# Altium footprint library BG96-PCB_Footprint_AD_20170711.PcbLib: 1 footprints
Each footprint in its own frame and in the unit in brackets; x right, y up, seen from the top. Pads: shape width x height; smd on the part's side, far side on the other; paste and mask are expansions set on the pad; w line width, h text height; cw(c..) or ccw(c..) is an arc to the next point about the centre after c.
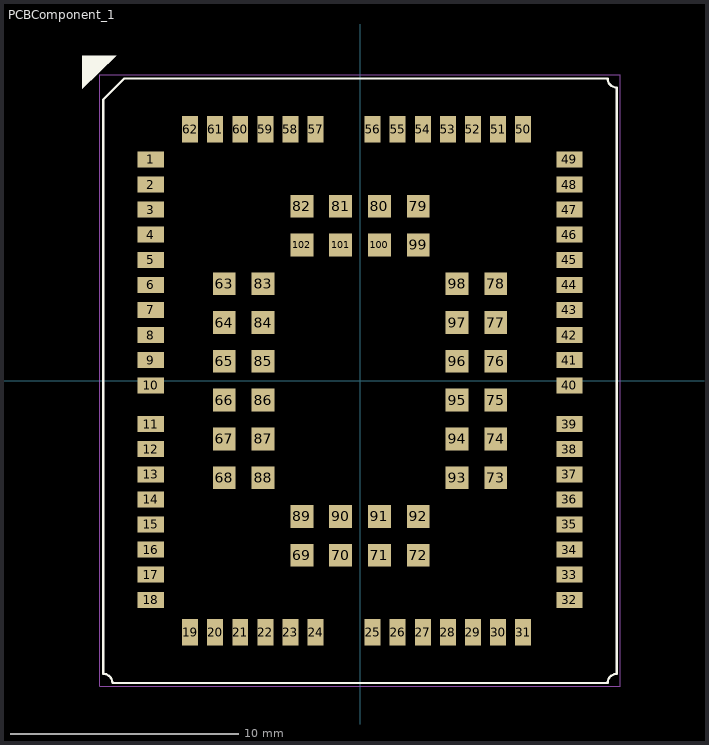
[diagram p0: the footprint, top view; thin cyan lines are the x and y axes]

## PCBComponent_1 [mm]
pads (102):
  rect 1.15x0.7 smd mask+0.05: 1(-9.175,9.7) 2(-9.175,8.6) 3(-9.175,7.5) 4(-9.175,6.4) 5(-9.175,5.3) 6(-9.175,4.2) 7(-9.175,3.1) 8(-9.175,2) 9(-9.175,0.9) 10(-9.175,-0.2) 11(-9.175,-1.9) 12(-9.175,-3) 13(-9.175,-4.1) 14(-9.175,-5.2) 15(-9.175,-6.3) 16(-9.175,-7.4) 17(-9.175,-8.5) 18(-9.175,-9.6) 32(9.175,-9.6) 33(9.175,-8.5) 34(9.175,-7.4) 35(9.175,-6.3) 36(9.175,-5.2) 37(9.175,-4.1) 38(9.175,-3) 39(9.175,-1.9) 40(9.175,-0.2) 41(9.175,0.9) 42(9.175,2) 43(9.175,3.1) 44(9.175,4.2) 45(9.175,5.3) 46(9.175,6.4) 47(9.175,7.5) 48(9.175,8.6) 49(9.175,9.7)
  rect 0.7x1.15 smd mask+0.05: 19(-7.45,-11.025) 20(-6.35,-11.025) 21(-5.25,-11.025) 22(-4.15,-11.025) 23(-3.05,-11.025) 24(-1.95,-11.025) 25(0.55,-11.025) 26(1.65,-11.025) 27(2.75,-11.025) 28(3.85,-11.025) 29(4.95,-11.025) 30(6.05,-11.025) 31(7.15,-11.025) 50(7.15,11.025) 51(6.05,11.025) 52(4.95,11.025) 53(3.85,11.025) 54(2.75,11.025) 55(1.65,11.025) 56(0.55,11.025) 57(-1.95,11.025) 58(-3.05,11.025) 59(-4.15,11.025) 60(-5.25,11.025) 61(-6.35,11.025) 62(-7.45,11.025)
  rect 1x1 smd mask+0.05: 63(-5.95,4.25) 64(-5.95,2.55) 65(-5.95,0.85) 66(-5.95,-0.85) 67(-5.95,-2.55) 68(-5.95,-4.25) 69(-2.55,-7.65) 70(-0.85,-7.65) 71(0.85,-7.65) 72(2.55,-7.65) 73(5.95,-4.25) 74(5.95,-2.55) 75(5.95,-0.85) 76(5.95,0.85) 77(5.95,2.55) 78(5.95,4.25) 79(2.55,7.65) 80(0.85,7.65) 81(-0.85,7.65) 82(-2.55,7.65) 83(-4.25,4.25) 84(-4.25,2.55) 85(-4.25,0.85) 86(-4.25,-0.85) 87(-4.25,-2.55) 88(-4.25,-4.25) 89(-2.55,-5.95) 90(-0.85,-5.95) 91(0.85,-5.95) 92(2.55,-5.95) 93(4.25,-4.25) 94(4.25,-2.55) 95(4.25,-0.85) 96(4.25,0.85) 97(4.25,2.55) 98(4.25,4.25) 99(2.55,5.95) 100(0.85,5.95) 101(-0.85,5.95) 102(-2.55,5.95)
Top Overlay:
  region: -12.18,14.24 -10.68,14.24 -12.18,12.79
  lines w0.1: -11.25,-12.85 cw(c-11.25,-13.25) -10.85,-13.25 10.85,-13.25 cw(c11.25,-13.25) 11.25,-12.85 11.25,12.85 cw(c11.25,13.25) 10.85,13.25 -10.33,13.25 -11.25,12.33 -11.25,-12.85
Mechanical 1:
  lines w0.01: -11.4,-13.4 11.4,-13.4 11.4,13.4 -11.4,13.4 -11.4,-13.4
